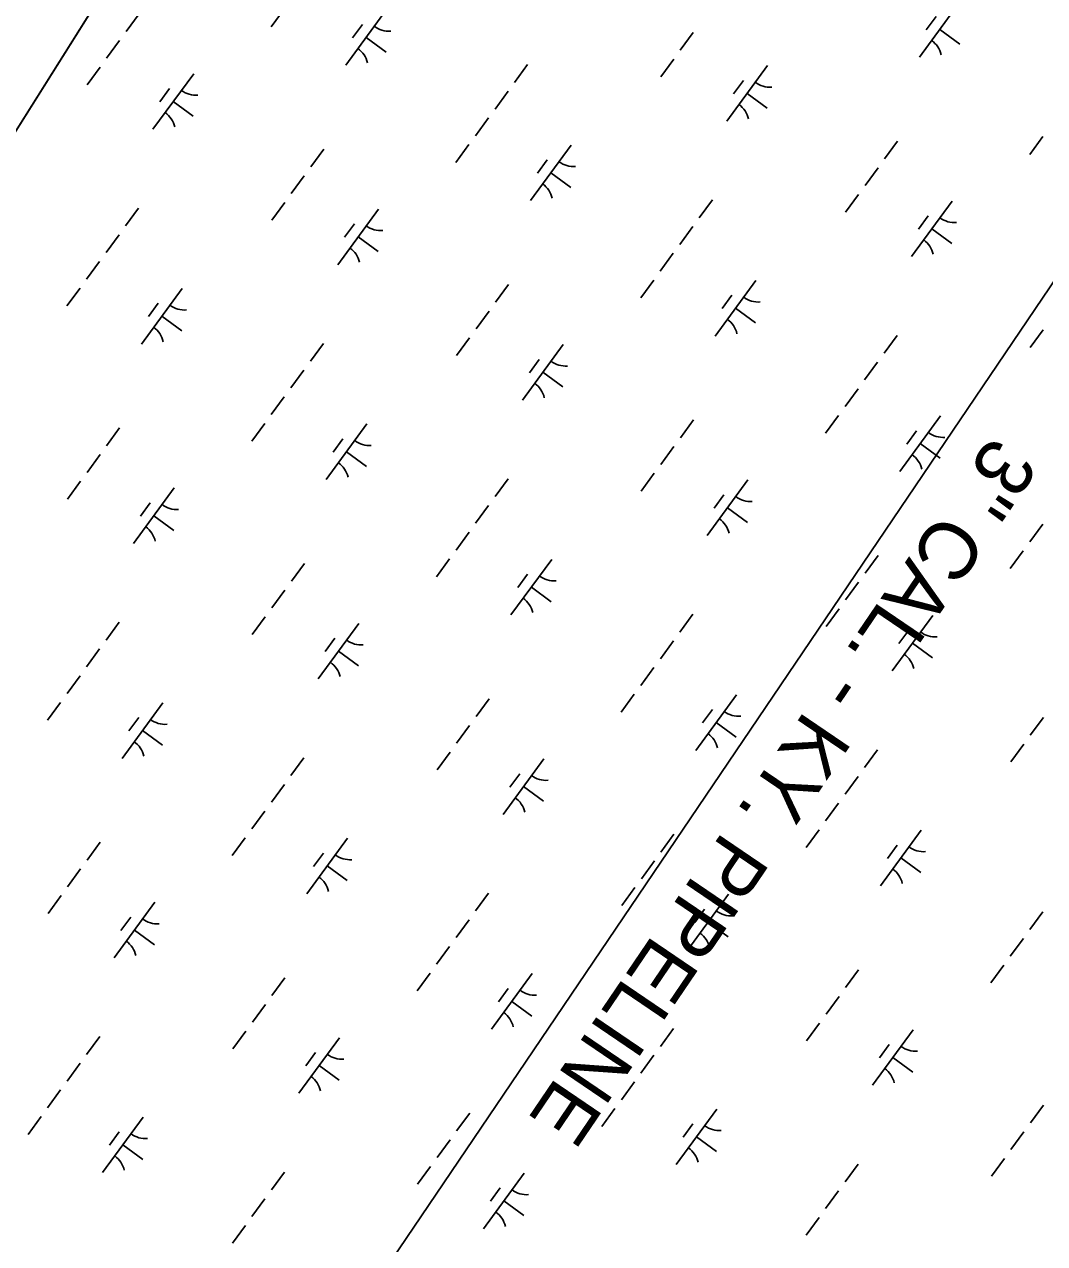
# Model space of a CAD drawing. Extents: x 3905714 to 3926767, y 183354 to 205755.
# Drawn here: x 3913898 to 3914639, y 191522 to 192407 of the extents above; entities that cross this region are included whole.
import ezdxf

# ---------------------------------------------------------------- set-up
doc = ezdxf.new("R2010")
doc.units = 0
for name, color, linetype in [('V-TOPO-SHOR', 7, 'Continuous'), ('V-UTIL-IDEN', 7, 'Continuous'), ('V-UTIL-LINE', 7, 'Continuous'), ('V-WETL-SWMP', 7, 'Continuous')]:
    doc.layers.add(name, color=color, linetype=linetype)

msp = doc.modelspace()

# ---------------------------------------------------------------- linework, layer by layer
at = {"layer": 'V-TOPO-SHOR'}
msp.add_lwpolyline([(3913958.04, 192435.21), (3913871.05, 192297.3), (3913838.92, 192251.52), (3913829.98, 192241.13), (3913816.89, 192235.46), (3913801.72, 192232.94), (3913788.66, 192231.45), (3913770.87, 192226.33), (3913752.95, 192213.22), (3913738.52, 192200.08)], dxfattribs=at)
at = {"layer": 'V-UTIL-LINE'}
msp.add_lwpolyline([(3920382.72, 200123.13), (3919431.34, 198911.04), (3917639.74, 196643.01), (3912670.96, 189304.15), (3911629.35, 187953.28)], dxfattribs=at)
at = {"layer": 'V-WETL-SWMP'}
for p, q in [((3913958.05, 192435.22), (3913871.05, 192297.3)), ((3914086.32, 192417.71), (3914076.86, 192404.8)), ((3914160.5, 192417.38), (3914130.95, 192377.05)), ((3914577.18, 192423.21), (3914547.63, 192382.87)), ((3913980.91, 192414.42), (3913971.45, 192401.51)), ((3914143.05, 192406.62), (3914135.96, 192396.94)), ((3914559.72, 192412.44), (3914552.63, 192402.76)), ((3914145.73, 192397.22), (3914160.25, 192386.58)), ((3914383.4, 192400.88), (3914373.94, 192387.98)), ((3914562.4, 192403.04), (3914576.92, 192392.4)), ((3913966.72, 192395.06), (3913957.27, 192382.15)), ((3914369.21, 192381.52), (3914359.76, 192368.62)), ((3913952.54, 192375.7), (3913943.08, 192362.79)), ((3914020.55, 192370.87), (3913991, 192330.53)), ((3914263.05, 192377.48), (3914253.59, 192364.58)), ((3914437.22, 192376.69), (3914407.67, 192336.36)), ((3914419.77, 192365.93), (3914412.68, 192356.24)), ((3914003.1, 192360.1), (3913996, 192350.42)), ((3914248.87, 192358.12), (3914239.41, 192345.22)), ((3914422.45, 192356.53), (3914436.97, 192345.89)), ((3914005.77, 192350.7), (3914020.29, 192340.06)), ((3914234.68, 192338.76), (3914225.23, 192325.86)), ((3914220.5, 192319.4), (3914211.04, 192306.5)), ((3914294.68, 192319.08), (3914265.13, 192278.74)), ((3914531.76, 192321.94), (3914522.3, 192309.03)), ((3914637.17, 192325.23), (3914627.72, 192312.32)), ((3914115.09, 192316.11), (3914105.63, 192303.21)), ((3914277.23, 192308.31), (3914270.14, 192298.63)), ((3914517.58, 192302.58), (3914508.12, 192289.67)), ((3914100.9, 192296.75), (3914091.45, 192283.85)), ((3914279.91, 192298.91), (3914294.43, 192288.27)), ((3914503.39, 192283.22), (3914493.94, 192270.31)), ((3913980.56, 192273.35), (3913971.1, 192260.45)), ((3914086.72, 192277.39), (3914077.26, 192264.49)), ((3914397.23, 192279.18), (3914387.77, 192266.27)), ((3914571.4, 192278.39), (3914541.85, 192238.05)), ((3914154.73, 192272.56), (3914125.18, 192232.23)), ((3914553.95, 192267.62), (3914546.86, 192257.94)), ((3914137.27, 192261.79), (3914130.18, 192252.11)), ((3914383.05, 192259.82), (3914373.59, 192246.91)), ((3914556.63, 192258.22), (3914571.15, 192247.58)), ((3913966.37, 192253.99), (3913956.92, 192241.09)), ((3914139.95, 192252.39), (3914154.47, 192241.76)), ((3914368.86, 192240.46), (3914359.41, 192227.55)), ((3913952.19, 192234.63), (3913942.73, 192221.73)), ((3914354.68, 192221.1), (3914345.22, 192208.19)), ((3914428.86, 192220.77), (3914399.31, 192180.44)), ((3913938, 192215.27), (3913928.55, 192202.37)), ((3914012.19, 192214.95), (3913982.64, 192174.61)), ((3914249.27, 192217.81), (3914239.81, 192204.9)), ((3913994.74, 192204.18), (3913987.64, 192194.5)), ((3914411.41, 192210), (3914404.32, 192200.32)), ((3913997.41, 192194.78), (3914011.93, 192184.14)), ((3914235.08, 192198.45), (3914225.63, 192185.54)), ((3914414.09, 192200.6), (3914428.61, 192189.97)), ((3914637.57, 192184.91), (3914628.12, 192172)), ((3914220.9, 192179.09), (3914211.44, 192166.18)), ((3914531.41, 192180.87), (3914521.95, 192167.97)), ((3914114.74, 192175.05), (3914105.28, 192162.14)), ((3914288.91, 192174.25), (3914259.36, 192133.92)), ((3914271.45, 192163.49), (3914264.36, 192153.81)), ((3914517.23, 192161.51), (3914507.77, 192148.61)), ((3914100.55, 192155.69), (3914091.1, 192142.78)), ((3914274.13, 192154.09), (3914288.65, 192143.45)), ((3914503.04, 192142.15), (3914493.59, 192129.25)), ((3914086.37, 192136.33), (3914076.91, 192123.42)), ((3914488.86, 192122.79), (3914479.4, 192109.89)), ((3913966.77, 192113.68), (3913957.32, 192100.77)), ((3914072.18, 192116.97), (3914062.73, 192104.06)), ((3914146.37, 192116.64), (3914116.82, 192076.31)), ((3914383.45, 192119.5), (3914373.99, 192106.59)), ((3914563.04, 192122.46), (3914533.49, 192082.13)), ((3914128.91, 192105.87), (3914121.82, 192096.19)), ((3914545.59, 192111.7), (3914538.5, 192102.02)), ((3914131.59, 192096.47), (3914146.11, 192085.83)), ((3914369.26, 192100.14), (3914359.81, 192087.23)), ((3914548.27, 192102.3), (3914562.79, 192091.66)), ((3913952.59, 192094.32), (3913943.13, 192081.41)), ((3914355.08, 192080.78), (3914345.62, 192067.87)), ((3913938.4, 192074.96), (3913928.95, 192062.05)), ((3914006.41, 192070.12), (3913976.86, 192029.79)), ((3914248.92, 192076.74), (3914239.46, 192063.83)), ((3914423.09, 192075.95), (3914393.54, 192035.62)), ((3914405.63, 192065.18), (3914398.54, 192055.5)), ((3913988.96, 192059.36), (3913981.87, 192049.68)), ((3914234.73, 192057.38), (3914225.28, 192044.47)), ((3914408.31, 192055.78), (3914422.83, 192045.14)), ((3913991.64, 192049.96), (3914006.16, 192039.32)), ((3914637.22, 192043.85), (3914627.77, 192030.94)), ((3914220.55, 192038.02), (3914211.09, 192025.11)), ((3914206.36, 192018.66), (3914196.91, 192005.75)), ((3914280.55, 192018.33), (3914251, 191978)), ((3914517.63, 192021.19), (3914508.17, 192008.29)), ((3914623.04, 192024.49), (3914613.58, 192011.58)), ((3914100.95, 192015.37), (3914091.5, 192002.46)), ((3914263.09, 192007.57), (3914256, 191997.89)), ((3914503.44, 192001.83), (3914493.99, 191988.93)), ((3914086.77, 191996.01), (3914077.31, 191983.1)), ((3914265.77, 191998.17), (3914280.29, 191987.53)), ((3914489.26, 191982.47), (3914479.8, 191969.57)), ((3913966.42, 191972.61), (3913956.97, 191959.7)), ((3914072.58, 191976.65), (3914063.13, 191963.74)), ((3914383.1, 191978.44), (3914373.64, 191965.53)), ((3914557.27, 191977.64), (3914527.72, 191937.31)), ((3914140.59, 191971.82), (3914111.04, 191931.48)), ((3914539.81, 191966.88), (3914532.72, 191957.2)), ((3914123.14, 191961.05), (3914116.05, 191951.37)), ((3914368.91, 191959.08), (3914359.46, 191946.17)), ((3914542.49, 191957.48), (3914557.01, 191946.84)), ((3913952.24, 191953.25), (3913942.78, 191940.34)), ((3914125.82, 191951.65), (3914140.34, 191941.01)), ((3914354.73, 191939.72), (3914345.27, 191926.81)), ((3913938.05, 191933.89), (3913928.6, 191920.98)), ((3914340.54, 191920.36), (3914331.09, 191907.45)), ((3914414.73, 191920.03), (3914385.18, 191879.69)), ((3913923.87, 191914.53), (3913914.41, 191901.62)), ((3913998.05, 191914.2), (3913968.5, 191873.87)), ((3914235.13, 191917.06), (3914225.68, 191904.16)), ((3913980.6, 191903.44), (3913973.51, 191893.76)), ((3914397.27, 191909.26), (3914390.18, 191899.58)), ((3914637.62, 191903.53), (3914628.16, 191890.62)), ((3913983.28, 191894.04), (3913997.8, 191883.4)), ((3914220.95, 191897.7), (3914211.49, 191884.8)), ((3914399.95, 191899.86), (3914414.47, 191889.22)), ((3914623.44, 191884.17), (3914613.98, 191871.26)), ((3914206.76, 191878.34), (3914197.31, 191865.44)), ((3914517.27, 191880.13), (3914507.82, 191867.22)), ((3914100.6, 191874.3), (3914091.15, 191861.4)), ((3914274.77, 191873.51), (3914245.22, 191833.18)), ((3914257.32, 191862.75), (3914250.23, 191853.07)), ((3914503.09, 191860.77), (3914493.63, 191847.86)), ((3914086.42, 191854.94), (3914076.96, 191842.04)), ((3914260, 191853.35), (3914274.52, 191842.71)), ((3914488.91, 191841.41), (3914479.45, 191828.5)), ((3914072.23, 191835.58), (3914062.78, 191822.68)), ((3914474.72, 191822.05), (3914465.27, 191809.14)), ((3914548.91, 191821.72), (3914519.36, 191781.39)), ((3913952.64, 191812.93), (3913943.18, 191800.03)), ((3914058.05, 191816.22), (3914048.59, 191803.32)), ((3914132.23, 191815.9), (3914102.68, 191775.56)), ((3914369.31, 191818.76), (3914359.85, 191805.85)), ((3914114.78, 191805.13), (3914107.69, 191795.45)), ((3914531.45, 191810.95), (3914524.36, 191801.27)), ((3914117.46, 191795.73), (3914131.98, 191785.09)), ((3914355.13, 191799.4), (3914345.67, 191786.49)), ((3914534.13, 191801.55), (3914548.65, 191790.92)), ((3913938.45, 191793.57), (3913929, 191780.67)), ((3914340.94, 191780.04), (3914331.49, 191767.13)), ((3913924.27, 191774.21), (3913914.81, 191761.31)), ((3913992.28, 191769.38), (3913962.73, 191729.05)), ((3914234.78, 191776), (3914225.32, 191763.09)), ((3914408.95, 191775.21), (3914379.4, 191734.87)), ((3914391.5, 191764.44), (3914384.41, 191754.76)), ((3914637.27, 191762.46), (3914627.81, 191749.56)), ((3913974.83, 191758.61), (3913967.73, 191748.93)), ((3914220.6, 191756.64), (3914211.14, 191743.73)), ((3914394.18, 191755.04), (3914408.7, 191744.4)), ((3913977.5, 191749.21), (3913992.02, 191738.58)), ((3914623.09, 191743.1), (3914613.63, 191730.2)), ((3914206.41, 191737.28), (3914196.96, 191724.37)), ((3914192.23, 191717.92), (3914182.77, 191705.01)), ((3914266.41, 191717.59), (3914236.86, 191677.26)), ((3914503.49, 191720.45), (3914494.03, 191707.55)), ((3914608.9, 191723.74), (3914599.45, 191710.84)), ((3914086.82, 191714.63), (3914077.36, 191701.72)), ((3914248.96, 191706.82), (3914241.87, 191697.14)), ((3914489.31, 191701.09), (3914479.85, 191688.18)), ((3914072.63, 191695.27), (3914063.18, 191682.36)), ((3914251.64, 191697.42), (3914266.16, 191686.79)), ((3914475.12, 191681.73), (3914465.67, 191668.82)), ((3913952.29, 191671.87), (3913942.83, 191658.96)), ((3914058.45, 191675.91), (3914048.99, 191663)), ((3914368.96, 191677.69), (3914359.5, 191664.79)), ((3914543.13, 191676.9), (3914513.58, 191636.57)), ((3914126.46, 191671.08), (3914096.91, 191630.74)), ((3914525.68, 191666.13), (3914518.59, 191656.45)), ((3914109, 191660.31), (3914101.91, 191650.63)), ((3914354.78, 191658.33), (3914345.32, 191645.43)), ((3914528.36, 191656.73), (3914542.88, 191646.1)), ((3913938.1, 191652.51), (3913928.65, 191639.6)), ((3914111.68, 191650.91), (3914126.2, 191640.27)), ((3914340.59, 191638.97), (3914331.14, 191626.07)), ((3913923.92, 191633.15), (3913914.46, 191620.24)), ((3914326.41, 191619.61), (3914316.95, 191606.71)), ((3914400.59, 191619.28), (3914371.04, 191578.95)), ((3914637.67, 191622.15), (3914628.21, 191609.24)), ((3913909.73, 191613.79), (3913900.28, 191600.88)), ((3913983.92, 191613.46), (3913954.37, 191573.13)), ((3914221, 191616.32), (3914211.54, 191603.41)), ((3913966.47, 191602.69), (3913959.37, 191593.01)), ((3914383.14, 191608.52), (3914376.05, 191598.84)), ((3914623.49, 191602.79), (3914614.03, 191589.88)), ((3913969.14, 191593.29), (3913983.66, 191582.65)), ((3914206.81, 191596.96), (3914197.36, 191584.05)), ((3914385.82, 191599.12), (3914400.34, 191588.48)), ((3914609.3, 191583.43), (3914599.85, 191570.52)), ((3914192.63, 191577.6), (3914183.17, 191564.69)), ((3914503.14, 191579.39), (3914493.68, 191566.48)), ((3914086.47, 191573.56), (3914077.01, 191560.65)), ((3914260.64, 191572.77), (3914231.09, 191532.44)), ((3914243.18, 191562), (3914236.09, 191552.32)), ((3914488.96, 191560.03), (3914479.5, 191547.12)), ((3914072.28, 191554.2), (3914062.83, 191541.29)), ((3914245.86, 191552.6), (3914260.38, 191541.96)), ((3914474.77, 191540.67), (3914465.32, 191527.76)), ((3914058.1, 191534.84), (3914048.64, 191521.93))]:
    msp.add_line(p, q, dxfattribs=at)
for centre, start, end in [((3914162.24, 192419.36), 232.99998, 274.54364), ((3914129.6, 192374.79), 12.99998, 54.54364), ((3914546.27, 192380.62), 12.99998, 54.54364), ((3914438.96, 192378.67), 232.99998, 274.54364), ((3914022.29, 192372.84), 232.99998, 274.54364), ((3914406.31, 192334.1), 12.99998, 54.54364), ((3913989.64, 192328.28), 12.99998, 54.54364), ((3914296.42, 192321.05), 232.99998, 274.54364), ((3914263.77, 192276.49), 12.99998, 54.54364), ((3914573.14, 192280.36), 232.99998, 274.54364), ((3914156.47, 192274.54), 232.99998, 274.54364), ((3914540.49, 192235.8), 12.99998, 54.54364), ((3914123.82, 192229.97), 12.99998, 54.54364), ((3914013.93, 192216.92), 232.99998, 274.54364), ((3914430.6, 192222.74), 232.99998, 274.54364), ((3913981.28, 192172.36), 12.99998, 54.54364), ((3914397.95, 192178.18), 12.99998, 54.54364), ((3914290.65, 192176.23), 232.99998, 274.54364), ((3914258, 192131.67), 12.99998, 54.54364), ((3914564.78, 192124.44), 232.99998, 274.54364), ((3914148.11, 192118.61), 232.99998, 274.54364), ((3914115.46, 192074.05), 12.99998, 54.54364), ((3914532.13, 192079.88), 12.99998, 54.54364), ((3914424.83, 192077.92), 232.99998, 274.54364), ((3914008.15, 192072.1), 232.99998, 274.54364), ((3914392.18, 192033.36), 12.99998, 54.54364), ((3913975.51, 192027.54), 12.99998, 54.54364), ((3914282.29, 192020.31), 232.99998, 274.54364), ((3914249.64, 191975.74), 12.99998, 54.54364), ((3914559.01, 191979.62), 232.99998, 274.54364), ((3914142.33, 191973.79), 232.99998, 274.54364), ((3914526.36, 191935.05), 12.99998, 54.54364), ((3914109.68, 191929.23), 12.99998, 54.54364), ((3913999.79, 191916.18), 232.99998, 274.54364), ((3914416.47, 191922), 232.99998, 274.54364), ((3913967.15, 191871.61), 12.99998, 54.54364), ((3914383.82, 191877.44), 12.99998, 54.54364), ((3914276.51, 191875.49), 232.99998, 274.54364), ((3914243.86, 191830.92), 12.99998, 54.54364), ((3914550.65, 191823.7), 232.99998, 274.54364), ((3914133.97, 191817.87), 232.99998, 274.54364), ((3914101.32, 191773.31), 12.99998, 54.54364), ((3914518, 191779.13), 12.99998, 54.54364), ((3914410.69, 191777.18), 232.99998, 274.54364), ((3913994.02, 191771.36), 232.99998, 274.54364), ((3914378.04, 191732.62), 12.99998, 54.54364), ((3913961.37, 191726.79), 12.99998, 54.54364), ((3914268.15, 191719.56), 232.99998, 274.54364), ((3914235.5, 191675), 12.99998, 54.54364), ((3914544.87, 191678.87), 232.99998, 274.54364), ((3914128.2, 191673.05), 232.99998, 274.54364), ((3914512.22, 191634.31), 12.99998, 54.54364), ((3914095.55, 191628.49), 12.99998, 54.54364), ((3913985.66, 191615.43), 232.99998, 274.54364), ((3914402.33, 191621.26), 232.99998, 274.54364), ((3913953.01, 191570.87), 12.99998, 54.54364), ((3914369.68, 191576.7), 12.99998, 54.54364), ((3914262.38, 191574.74), 232.99998, 274.54364), ((3914229.73, 191530.18), 12.99998, 54.54364)]:
    msp.add_arc(centre, 17.62, start, end, dxfattribs=at)

# ---------------------------------------------------------------- texts
at = {"layer": 'V-UTIL-IDEN'}
msp.add_text('3" CAL. - KY. PIPELINE', height=41.9999, rotation=235.81796, dxfattribs=at).set_placement((3914600.5, 192109.49))

doc.saveas('drawing.dxf')
